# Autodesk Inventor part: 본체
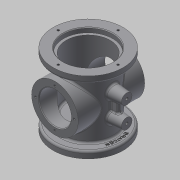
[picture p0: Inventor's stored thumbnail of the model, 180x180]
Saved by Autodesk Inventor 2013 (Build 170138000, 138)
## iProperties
Created: 2017-08
Part Number: 본체
Material: 일반
Document SubType Name: Modeling
Designer: mduedu
Density: 2.71 g/cm^3
Mass: 872.327 g
Surface Area: 642.238 cm^2
Volume: 321.892 cm^3
Author: mduedu
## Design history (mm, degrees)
sketch "스케치1"
  geometry: C1 r 52.5 at (0, 0); 1 further point
  constraints: 1 centre point, 1 coincident
  dimensions: "d110" = 105 diameter of C1
extrude "돌출1" new body sketch "스케치1" distance "d5" = 10; taper "d6" = 0 deg
sketch "스케치2"
  geometry: C1 r 38 at (0, 0); 1 further point
  constraints: 1 centre point, 1 coincident
  dimensions: "d111" = 76 diameter of C1
extrude "돌출2" join sketch "스케치2" distance "d12" = 88; taper "d13" = 0 deg
sketch "스케치3"
  geometry: C1 r 52.5 at (0, 0); 1 further point
  constraints: 1 centre point, 1 coincident
  dimensions: "d114" = 105 diameter of C1
extrude "돌출3" join sketch "스케치3" distance "d19" = 10; taper "d20" = 0 deg
sketch "스케치4"
  geometry: C1 r 33 at (0, 0); 1 further point
  constraints: 1 centre point, 1 coincident
  dimensions: "d115" = 66 diameter of C1
extrude "돌출4" cut sketch "스케치4" distance "d26" = 86; taper "d27" = 0 deg
sketch "스케치5"
  geometry: C1 r 37 at (0, 0); 1 further point
  constraints: 1 centre point, 1 coincident
  dimensions: "d116" = 74 diameter of C1
extrude "돌출5" cut sketch "스케치5" distance "d29" = 7; taper "d30" = 0 deg
node "작업 평면1"
sketch "스케치18"
  geometry: L1 (-52.5, 0)-(52.5, 0) reference; C1 r 35 at (0, 54); 1 further point
  constraints: 1 centre point, 1 vertical alignment
  dimensions: "d118" = 70 diameter of C1; "d119" = 54 distance from line of C1.centre L1
extrude "돌출9" join sketch "스케치18" stored distance "d120" = 10; taper "d121" = 0 deg
hole "구멍8" diameter "d124" = 48; stored, may be unused: countersink angle "d128" = 90 deg, drill point angle "d130" = 118 deg; dims "d122" = 10, "d123" = 10, "d125" = 6, "d126" = 4, "d127" = 2, "d129" = 8
sketch "스케치9"
  geometry: C1 r 34 at (0, 0); 1 further point
  constraints: 1 centre point, 1 coincident
  dimensions: "d131" = 68 diameter of C1
extrude "돌출8" cut sketch "스케치9" distance "d43" = 16; taper "d44" = 0 deg
node "작업 평면2"
fillet "모깎기9" dims "d137" = 3
fillet "모깎기10" dims "d138" = 3
chamfer "모따기2" distance "d139" = 1; stored, may be unused: second distance "d140" = 2, angle "d141" = 45 deg
fillet "모깎기11" dims "d142" = 3
fillet "모깎기12" dims "d143" = 3
fillet "모깎기13" dims "d144" = 3
node "작업 평면3"
sketch "스케치20"
  geometry: L1 (0, 52.5)-(0, -52.5) reference; L2 (108, -52.5)-(108, 52.5) reference; C1 r 8 at (38, 0); C2 r 8 at (70, 0); 1 further point
  constraints: 2 centre point, 2 horizontal alignment
  dimensions: "d203" = 16 diameter of C1; "d204" = 16 diameter of C2; "d205" = 30 distance edge to line of C1 L1; "d206" = 30 distance edge to line of C2 L2; "d207" = 48 dimension on C2 C1 (derived)
extrude "돌출10" join sketch "스케치20" stored distance "d152" = 10; taper "d153" = 5 deg
sketch "스케치27"
  geometry: L1 (58, 62)-(38, 60.25) reference; L2 (58, 46)-(38, 47.75) reference; L3 (48, 61.125)-(48, 46.875); L4 (38, 13)-(38, 95) reference; 1 further point
  constraints: 2 end point, 2 midpoint, 1 vertical
  dimensions: "d208" = 10 distance between parallel lines of L3 L4
feature "리브1" sketch "스케치27" dims "d209" = 1, "d210" = 6, "d211" = 0, "d212" = 0, "d213" = 1, "d214" = 1
feature "면 기울기1" dims angle "d215" = 5 deg
fillet "모깎기15" dims "d216" = 3
fillet "모깎기16" dims "d217" = 3
fillet "모깎기17" dims "d218" = 3
sketch "스케치21"
  geometry: C1 r 8 at (0, 70) reference; C2 r 8 at (0, 38) reference; 3 further points
  constraints: 2 coincident
hole "구멍12" sketch "스케치21" at (0, 70), (0, 38) diameter "d219" = 4.134; stored, may be unused: countersink angle "d223" = 90 deg, drill point angle "d225" = 118 deg; dims "d220" = 6, "d221" = 4, "d222" = 2, "d224" = 8
sketch "스케치23"
  geometry: C1 r 15 at (0, 0); 1 further point
  constraints: 1 centre point, 1 coincident
  dimensions: "d168" = 30 diameter of C1
extrude "돌출12" cut sketch "스케치23" stored distance "d169" = 148.25; taper "d170" = 0 deg
sketch "스케치24"
  geometry: C1 r 43 at (0, 0); 1 further point
  constraints: 1 centre point, 1 coincident, 1 other
  dimensions: "d174" = 86 diameter of C1
feature "엠보싱3" sketch "스케치24" dims "d176" = 0.5, "d177" = 0
sketch "스케치25" dims "d178" = 58
  geometry: C1 r 35 at (0, 0) reference; 3 further points
  constraints: 2 vertical alignment, 1 coincident, 2 other
hole "구멍10" sketch "스케치25" at (0, 29) diameter "d179" = 3.242; stored, may be unused: countersink angle "d183" = 90 deg, drill point angle "d185" = 118 deg; dims "d180" = 4, "d181" = 4, "d182" = 2, "d184" = 6
sketch "스케치26" dims "d189" = 90
  geometry: 3 further points
  constraints: 2 vertical alignment, 1 coincident, 2 other
hole "구멍11" sketch "스케치26" at (0, 45) diameter "d190" = 3.242; stored, may be unused: countersink angle "d194" = 90 deg, drill point angle "d196" = 118 deg; dims "d191" = 4, "d192" = 4, "d193" = 2, "d195" = 6
chamfer "모따기4" distance "d200" = 1; stored, may be unused: second distance "d201" = 2, angle "d202" = 45 deg
node "솔리드1"
mirror "대칭2"
pattern_circular "원형 패턴1" dims angle "d187" = 360 deg
mirror "대칭3"
pattern_circular "원형 패턴2" dims angle "d198" = 360 deg
other parameters: "d147" = 58
